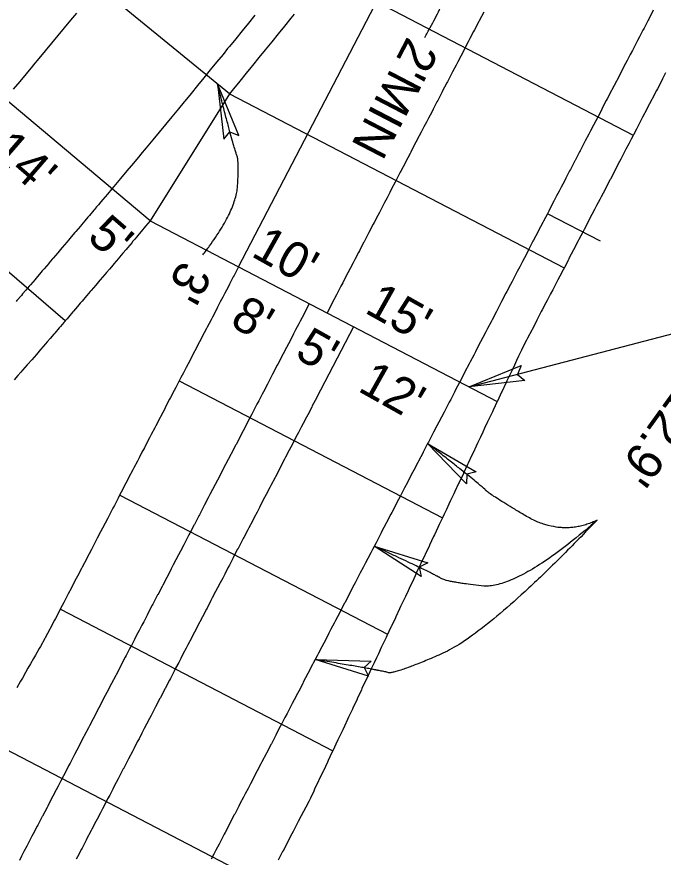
# Model space of a CAD drawing. Extents: x 2145147 to 2158018, y 137519 to 148068.
# Drawn here: x 2150427.2 to 2150492, y 143802 to 143886.4 of the extents above; entities that cross this region are included whole.
import ezdxf

# ---------------------------------------------------------------- set-up
doc = ezdxf.new("R2010")
doc.units = 0
for name, color, linetype in [('PR_Align_Ramp_B', 7, 'Continuous'), ('PR_Align_Service_C_Leader', 7, 'Continuous'), ('PR_Arrows', 7, 'Continuous'), ('PR_Dimensions', 7, 'Continuous'), ('PR_Joint_Contraction', 7, 'Continuous'), ('PR_Joint_Isolation', 7, 'Continuous'), ('PR_Joint_Long', 7, 'Continuous'), ('PR_Road_Concrete', 7, 'Continuous')]:
    doc.layers.add(name, color=color, linetype=linetype)

msp = doc.modelspace()

# ---------------------------------------------------------------- linework, layer by layer
at = {"layer": 'PR_Align_Ramp_B'}
msp.add_lwpolyline([(2150485.753, 143863.83), (2150480.431, 143866.6)], dxfattribs=at)
at = {"layer": 'PR_Align_Service_C_Leader'}
msp.add_lwpolyline([(2150472.601, 143849.219), (2150503.406, 143857.277), (2150523.033, 143884.125)], dxfattribs=at)
at = {"layer": 'PR_Arrows'}
msp.add_lwpolyline([(2150472.601, 143849.219), (2150477.794, 143851.352), (2150477.425, 143850.481), (2150478.173, 143849.866)], close=True, dxfattribs=at)
at = {"layer": 'PR_Dimensions'}
for points in [[(2150447.344, 143879.636), (2150447.998, 143874.06), (2150448.58, 143874.805), (2150449.48, 143874.449)], [(2150468.428, 143843.537), (2150473.278, 143840.709), (2150472.362, 143840.473), (2150472.328, 143839.505)], [(2150463.068, 143833.24), (2150468.431, 143831.579), (2150467.592, 143831.143), (2150467.778, 143830.193)], [(2150457.151, 143821.87), (2150462.762, 143821.705), (2150462.071, 143821.06), (2150462.504, 143820.194)]]:
    msp.add_lwpolyline(points, close=True, dxfattribs=at)
for points in [[(2150468.143, 143884.29), (2150470.819, 143888.915), (2150471.175, 143894.152), (2150470.668, 143895.218), (2150468.976, 143901.836)], [(2150445.878, 143862.457), (2150449.187, 143866.715), (2150449.543, 143871.953), (2150449.037, 143873.019), (2150447.344, 143879.636)], [(2150485.414, 143835.848), (2150481.891, 143834.132), (2150474.591, 143838.449), (2150473.817, 143839.339), (2150468.428, 143843.537)], [(2150485.414, 143835.848), (2150474.479, 143824.434), (2150464.997, 143820.349), (2150463.891, 143820.76), (2150457.151, 143821.87)], [(2150485.414, 143835.848), (2150477.393, 143828.84), (2150470.221, 143829.675), (2150469.266, 143830.367), (2150463.068, 143833.24)]]:
    msp.add_open_spline(points, degree=2, dxfattribs=at)
at = {"layer": 'PR_Joint_Contraction'}
for p, q in [((2150448.565, 143878.639), (2150428.687, 143894.877)), ((2150458.166, 143890.552), (2150489.043, 143874.482)), ((2150448.565, 143878.639), (2150482.117, 143861.177)), ((2150432.093, 143855.849), (2150411.095, 143873.864)), ((2150443.512, 143849.816), (2150469.909, 143836.078)), ((2150437.557, 143838.373), (2150464.411, 143824.397)), ((2150431.602, 143826.93), (2150458.913, 143812.716)), ((2150424.26, 143813.841), (2150452.174, 143799.313))]:
    msp.add_line(p, q, dxfattribs=at)
at = {"layer": 'PR_Joint_Isolation'}
msp.add_line((2150440.597, 143865.876), (2150419.424, 143883.685), dxfattribs=at)
msp.add_lwpolyline([(2150449.468, 143861.259), (2150475.406, 143847.76)], dxfattribs=at)
at = {"layer": 'PR_Joint_Long'}
msp.add_line((2150449.468, 143861.259), (2150470.243, 143901.177), dxfattribs=at)
for points in [[(2150491.049, 143887.003), (2150490.588, 143886.116), (2150490.53, 143886.004), (2150490.126, 143885.228), (2150490.005, 143884.996), (2150489.664, 143884.341), (2150489.481, 143883.988), (2150489.203, 143883.454), (2150488.956, 143882.98), (2150488.741, 143882.567), (2150488.431, 143881.972), (2150488.279, 143881.68), (2150487.907, 143880.964), (2150487.818, 143880.793), (2150487.382, 143879.956), (2150487.356, 143879.906), (2150486.894, 143879.019), (2150486.857, 143878.948), (2150486.433, 143878.132), (2150486.333, 143877.94), (2150485.971, 143877.245), (2150485.808, 143876.932), (2150485.509, 143876.358), (2150485.284, 143875.924), (2150485.048, 143875.471), (2150484.759, 143874.916), (2150484.586, 143874.584), (2150484.234, 143873.908), (2150484.124, 143873.697), (2150483.71, 143872.9), (2150483.663, 143872.81), (2150483.201, 143871.923), (2150483.185, 143871.892), (2150482.739, 143871.036), (2150482.66, 143870.884), (2150482.278, 143870.149), (2150482.136, 143869.876), (2150481.816, 143869.262), (2150481.611, 143868.868), (2150481.354, 143868.375), (2150481.087, 143867.86), (2150480.893, 143867.487), (2150480.562, 143866.852), (2150480.431, 143866.6), (2150480.037, 143865.844), (2150479.969, 143865.713), (2150479.513, 143864.836), (2150479.508, 143864.826), (2150479.046, 143863.939), (2150478.988, 143863.828), (2150478.584, 143863.052), (2150478.463, 143862.82), (2150478.123, 143862.165), (2150477.939, 143861.812), (2150477.661, 143861.278), (2150477.414, 143860.804), (2150477.199, 143860.391), (2150476.89, 143859.796), (2150476.738, 143859.504), (2150476.365, 143858.788), (2150476.276, 143858.617), (2150475.84, 143857.78), (2150475.814, 143857.73), (2150475.353, 143856.843), (2150475.316, 143856.772), (2150474.891, 143855.956), (2150474.791, 143855.764), (2150474.429, 143855.069), (2150474.266, 143854.756), (2150473.968, 143854.182), (2150473.742, 143853.748), (2150473.506, 143853.295), (2150473.217, 143852.74), (2150473.044, 143852.408), (2150472.693, 143851.732), (2150472.583, 143851.521), (2150472.168, 143850.724), (2150472.121, 143850.633), (2150471.659, 143849.746), (2150471.644, 143849.717), (2150471.643, 143849.716), (2150471.198, 143848.859), (2150471.119, 143848.708), (2150470.736, 143847.972), (2150470.594, 143847.7), (2150470.274, 143847.085), (2150470.069, 143846.692), (2150469.813, 143846.198), (2150469.545, 143845.684), (2150469.351, 143845.311), (2150469.02, 143844.676), (2150468.889, 143844.424), (2150468.496, 143843.668), (2150468.428, 143843.537), (2150467.971, 143842.66), (2150467.966, 143842.65), (2150467.504, 143841.763), (2150467.446, 143841.652), (2150467.043, 143840.876), (2150466.922, 143840.644), (2150466.581, 143839.989), (2150466.397, 143839.636), (2150466.119, 143839.102), (2150465.872, 143838.628), (2150465.658, 143838.215), (2150465.348, 143837.62), (2150465.196, 143837.328), (2150464.823, 143836.612), (2150464.734, 143836.441), (2150464.299, 143835.604), (2150464.273, 143835.554), (2150463.811, 143834.667), (2150463.774, 143834.596), (2150463.349, 143833.779), (2150463.249, 143833.588), (2150462.887, 143832.892), (2150462.725, 143832.58), (2150462.426, 143832.005), (2150462.2, 143831.572), (2150461.964, 143831.118), (2150461.675, 143830.564), (2150461.502, 143830.231), (2150461.151, 143829.556), (2150461.041, 143829.344), (2150460.626, 143828.547), (2150460.579, 143828.457), (2150460.117, 143827.57), (2150460.102, 143827.539), (2150459.656, 143826.683), (2150459.577, 143826.531), (2150459.194, 143825.796), (2150459.052, 143825.523), (2150458.732, 143824.909), (2150458.528, 143824.515), (2150458.271, 143824.022), (2150458.003, 143823.507), (2150457.809, 143823.135), (2150457.478, 143822.499), (2150457.347, 143822.248), (2150456.954, 143821.491), (2150456.886, 143821.361), (2150456.429, 143820.483), (2150456.424, 143820.474), (2150455.962, 143819.587), (2150455.905, 143819.475), (2150455.501, 143818.7), (2150455.38, 143818.467), (2150455.039, 143817.813), (2150454.855, 143817.459), (2150454.577, 143816.926), (2150454.331, 143816.451), (2150454.116, 143816.038), (2150453.806, 143815.443), (2150453.654, 143815.151), (2150453.281, 143814.435), (2150453.192, 143814.264), (2150452.757, 143813.427), (2150452.731, 143813.377), (2150452.269, 143812.49), (2150452.232, 143812.419), (2150451.807, 143811.603), (2150451.708, 143811.411), (2150451.346, 143810.716), (2150451.183, 143810.403), (2150450.884, 143809.829), (2150450.658, 143809.395), (2150450.422, 143808.942), (2150450.134, 143808.387), (2150449.961, 143808.055), (2150449.609, 143807.379), (2150449.499, 143807.168), (2150449.084, 143806.371), (2150449.037, 143806.281), (2150448.576, 143805.394), (2150448.56, 143805.363), (2150448.114, 143804.507), (2150448.035, 143804.355), (2150447.652, 143803.62), (2150447.511, 143803.347), (2150447.191, 143802.733), (2150446.986, 143802.339), (2150446.729, 143801.846)], [(2150433.215, 143886.728), (2150432.624, 143886.01), (2150431.989, 143885.24), (2150431.353, 143884.47), (2150430.717, 143883.7), (2150430.08, 143882.932), (2150429.443, 143882.163), (2150428.887, 143881.495), (2150428.805, 143881.396), (2150428.166, 143880.629), (2150427.526, 143879.862), (2150426.886, 143879.096)], [(2150451.09, 143886.513), (2150450.456, 143885.727), (2150449.821, 143884.941), (2150449.185, 143884.155), (2150448.55, 143883.372), (2150448.377, 143883.16), (2150447.911, 143882.586), (2150447.273, 143881.802), (2150446.635, 143881.019), (2150445.996, 143880.237), (2150445.356, 143879.454), (2150444.715, 143878.673), (2150444.076, 143877.894), (2150444.029, 143877.837), (2150443.432, 143877.111), (2150442.79, 143876.332), (2150442.146, 143875.552), (2150441.502, 143874.774), (2150440.858, 143873.996), (2150440.213, 143873.218), (2150439.652, 143872.543), (2150439.565, 143872.439), (2150438.92, 143871.665), (2150438.272, 143870.889), (2150437.624, 143870.113), (2150436.977, 143869.34), (2150436.768, 143869.091), (2150436.765, 143869.087), (2150436.327, 143868.566), (2150436.315, 143868.551), (2150435.866, 143868.016), (2150435.676, 143867.791), (2150435.414, 143867.48), (2150435.239, 143867.271), (2150435.026, 143867.018), (2150434.962, 143866.942), (2150434.512, 143866.409), (2150434.374, 143866.245), (2150434.06, 143865.873), (2150433.723, 143865.474), (2150433.607, 143865.337), (2150433.156, 143864.804), (2150433.069, 143864.701), (2150432.702, 143864.269), (2150432.416, 143863.932), (2150432.248, 143863.734), (2150431.797, 143863.202), (2150431.761, 143863.16), (2150431.342, 143862.668), (2150431.107, 143862.391), (2150430.888, 143862.134), (2150430.796, 143862.027), (2150430.452, 143861.623), (2150430.432, 143861.599), (2150429.979, 143861.069), (2150429.795, 143860.854), (2150429.523, 143860.535), (2150429.14, 143860.087), (2150429.067, 143860.002), (2150428.613, 143859.472), (2150428.481, 143859.318), (2150428.156, 143858.939), (2150427.824, 143858.552), (2150427.699, 143858.407), (2150427.244, 143857.878), (2150427.164, 143857.785)], [(2150455.035, 143886.632), (2150454.696, 143886.209), (2150454.061, 143885.42), (2150453.426, 143884.631), (2150452.79, 143883.842), (2150452.153, 143883.054), (2150451.516, 143882.267), (2150450.878, 143881.48), (2150450.707, 143881.27), (2150450.239, 143880.693), (2150449.599, 143879.908), (2150448.959, 143879.122), (2150448.565, 143878.639), (2150440.597, 143865.876)], [(2150474.05, 143886.831), (2150473.589, 143885.944), (2150473.552, 143885.873), (2150473.127, 143885.057), (2150473.027, 143884.865), (2150472.665, 143884.17), (2150472.502, 143883.857), (2150472.204, 143883.283), (2150471.978, 143882.849), (2150471.742, 143882.396), (2150471.453, 143881.841), (2150471.28, 143881.509), (2150470.928, 143880.833), (2150470.819, 143880.622), (2150470.404, 143879.825), (2150470.357, 143879.735), (2150469.895, 143878.848), (2150469.879, 143878.817), (2150469.434, 143877.961), (2150469.355, 143877.809), (2150468.972, 143877.074), (2150468.83, 143876.801), (2150468.51, 143876.187), (2150468.305, 143875.793), (2150468.049, 143875.3), (2150467.781, 143874.785), (2150467.587, 143874.413), (2150467.256, 143873.777), (2150467.125, 143873.525), (2150466.731, 143872.769), (2150466.663, 143872.638), (2150466.207, 143871.761), (2150466.202, 143871.751), (2150465.74, 143870.864), (2150465.682, 143870.753), (2150465.278, 143869.977), (2150465.158, 143869.745), (2150464.817, 143869.09), (2150464.633, 143868.737), (2150464.355, 143868.203), (2150464.108, 143867.729), (2150463.893, 143867.316), (2150463.584, 143866.721), (2150463.432, 143866.429), (2150463.059, 143865.713), (2150462.97, 143865.542), (2150462.534, 143864.705), (2150462.508, 143864.655), (2150462.047, 143863.768), (2150462.01, 143863.697), (2150461.585, 143862.881), (2150461.485, 143862.689), (2150461.123, 143861.994), (2150460.961, 143861.681), (2150460.662, 143861.107), (2150460.436, 143860.673), (2150460.2, 143860.22), (2150459.911, 143859.665), (2150459.738, 143859.333), (2150459.387, 143858.657), (2150459.277, 143858.446), (2150458.862, 143857.649), (2150458.815, 143857.559), (2150458.338, 143856.643)], [(2150456.564, 143857.566), (2150456.118, 143856.708), (2150456.04, 143856.558), (2150455.656, 143855.821), (2150455.514, 143855.549), (2150455.193, 143854.932), (2150454.989, 143854.539), (2150454.733, 143854.047), (2150454.465, 143853.533), (2150454.271, 143853.16), (2150453.94, 143852.524), (2150453.415, 143851.515), (2150453.348, 143851.385), (2150452.884, 143850.494), (2150452.879, 143850.484), (2150452.425, 143849.613), (2150452.366, 143849.501), (2150451.963, 143848.724), (2150451.842, 143848.493), (2150451.501, 143847.838), (2150451.317, 143847.485), (2150451.038, 143846.949), (2150450.792, 143846.475), (2150450.578, 143846.064), (2150450.268, 143845.469), (2150450.116, 143845.177), (2150449.743, 143844.461), (2150449.654, 143844.289), (2150449.218, 143843.452), (2150449.193, 143843.402), (2150448.731, 143842.516), (2150448.694, 143842.445), (2150448.168, 143841.435), (2150447.808, 143840.74), (2150447.645, 143840.429), (2150447.346, 143839.854), (2150447.12, 143839.421), (2150446.595, 143838.411), (2150446.423, 143838.079), (2150446.071, 143837.404), (2150445.961, 143837.192), (2150445.545, 143836.394), (2150445.497, 143836.302), (2150445.042, 143835.427), (2150445.027, 143835.397), (2150444.577, 143834.533), (2150444.498, 143834.382), (2150444.114, 143833.644), (2150443.971, 143833.37), (2150443.653, 143832.757), (2150443.448, 143832.364), (2150443.191, 143831.871), (2150442.923, 143831.356), (2150442.729, 143830.983), (2150442.399, 143830.347), (2150442.268, 143830.097), (2150441.875, 143829.341), (2150441.807, 143829.211), (2150441.361, 143828.356), (2150441.356, 143828.346), (2150440.882, 143827.433), (2150440.824, 143827.322), (2150440.421, 143826.548), (2150440.3, 143826.315), (2150439.958, 143825.66), (2150439.775, 143825.306), (2150439.498, 143824.775), (2150439.251, 143824.299), (2150439.036, 143823.887), (2150438.726, 143823.292), (2150438.574, 143822.999), (2150438.202, 143822.283), (2150438.113, 143822.113), (2150437.677, 143821.275), (2150437.651, 143821.225), (2150437.189, 143820.339), (2150437.152, 143820.267), (2150436.728, 143819.451), (2150436.266, 143818.565), (2150436.103, 143818.252), (2150435.803, 143817.676), (2150435.578, 143817.242), (2150435.343, 143816.791), (2150435.054, 143816.236), (2150434.881, 143815.904), (2150434.529, 143815.228), (2150434.419, 143815.016), (2150434.005, 143814.22), (2150433.959, 143814.131), (2150433.494, 143813.24), (2150433.479, 143813.209), (2150433.034, 143812.355), (2150432.573, 143811.468), (2150432.431, 143811.196), (2150432.111, 143810.582), (2150431.906, 143810.188), (2150431.648, 143809.694), (2150431.382, 143809.179), (2150431.188, 143808.808), (2150430.857, 143808.172), (2150430.726, 143807.921), (2150430.333, 143807.165), (2150430.264, 143807.034), (2150429.8, 143806.14), (2150429.796, 143806.131), (2150429.342, 143805.26), (2150429.284, 143805.149), (2150428.879, 143804.372), (2150428.758, 143804.139), (2150428.418, 143803.484), (2150428.234, 143803.132), (2150427.956, 143802.598), (2150427.709, 143802.124), (2150427.494, 143801.71)], [(2150461.003, 143855.256), (2150457.283, 143848.117), (2150457.278, 143848.106), (2150456.865, 143847.314), (2150456.804, 143847.196), (2150456.399, 143846.416), (2150456.281, 143846.19), (2150455.939, 143845.534), (2150455.755, 143845.18), (2150455.477, 143844.646), (2150455.224, 143844.162), (2150455.01, 143843.748), (2150454.705, 143843.163), (2150454.553, 143842.871), (2150454.18, 143842.155), (2150454.088, 143841.978), (2150453.652, 143841.14), (2150453.629, 143841.094), (2150453.169, 143840.212), (2150453.131, 143840.138), (2150452.711, 143839.331), (2150452.611, 143839.14), (2150452.239, 143838.426), (2150452.077, 143838.114), (2150451.784, 143837.55), (2150451.558, 143837.116), (2150451.321, 143836.661), (2150451.031, 143836.106), (2150450.855, 143835.766), (2150450.502, 143835.088), (2150450.394, 143834.879), (2150449.986, 143834.096), (2150449.94, 143834.007), (2150449.393, 143832.957), (2150449.378, 143832.926), (2150449.012, 143832.223), (2150448.933, 143832.071), (2150448.551, 143831.338), (2150448.409, 143831.065), (2150448.084, 143830.441), (2150447.88, 143830.048), (2150447.629, 143829.566), (2150447.361, 143829.052), (2150447.167, 143828.68), (2150446.837, 143828.046), (2150446.703, 143827.789), (2150446.313, 143827.037), (2150446.248, 143826.913), (2150445.86, 143826.169), (2150445.856, 143826.161), (2150445.293, 143825.081), (2150445.237, 143824.971), (2150444.856, 143824.239), (2150444.735, 143824.007), (2150444.395, 143823.355), (2150444.212, 143823.001), (2150443.93, 143822.461), (2150443.682, 143821.981), (2150443.473, 143821.581), (2150443.163, 143820.986), (2150443.011, 143820.694), (2150442.638, 143819.978), (2150442.546, 143819.801), (2150442.11, 143818.963), (2150442.087, 143818.917), (2150441.627, 143818.035), (2150441.59, 143817.964), (2150441.153, 143817.125), (2150441.054, 143816.933), (2150440.703, 143816.26), (2150440.541, 143815.947), (2150440.241, 143815.373), (2150440.016, 143814.939), (2150439.776, 143814.478), (2150439.488, 143813.924), (2150439.319, 143813.599), (2150438.967, 143812.924), (2150438.857, 143812.713), (2150438.444, 143811.92), (2150438.395, 143811.826), (2150437.921, 143810.913), (2150437.908, 143810.888), (2150437.47, 143810.047), (2150437.391, 143809.895), (2150437.001, 143809.147), (2150436.86, 143808.874), (2150436.548, 143808.276), (2150436.343, 143807.882), (2150436.087, 143807.39), (2150435.819, 143806.876), (2150435.622, 143806.497), (2150435.293, 143805.863), (2150435.165, 143805.619), (2150434.765, 143804.85), (2150434.698, 143804.721), (2150434.199, 143803.764), (2150434.191, 143803.748), (2150433.78, 143802.956), (2150433.724, 143802.849), (2150433.318, 143802.069), (2150433.197, 143801.837)]]:
    msp.add_lwpolyline(points, dxfattribs=at)
at = {"layer": 'PR_Road_Concrete'}
msp.add_line((2150440.597, 143865.876), (2150449.468, 143861.259), dxfattribs=at)
for points in [[(2150492.289, 143880.721), (2150491.979, 143880.126), (2150491.828, 143879.834), (2150491.455, 143879.118), (2150491.366, 143878.947), (2150490.93, 143878.11), (2150490.904, 143878.06), (2150490.443, 143877.172), (2150490.406, 143877.101), (2150489.981, 143876.285), (2150489.881, 143876.093), (2150489.519, 143875.398), (2150489.356, 143875.085), (2150489.058, 143874.511), (2150488.832, 143874.077), (2150488.596, 143873.624), (2150488.307, 143873.069), (2150488.134, 143872.737), (2150487.782, 143872.061), (2150487.673, 143871.85), (2150487.258, 143871.053), (2150487.211, 143870.963), (2150486.749, 143870.076), (2150486.733, 143870.045), (2150486.287, 143869.189), (2150486.209, 143869.037), (2150485.826, 143868.302), (2150485.684, 143868.029), (2150485.364, 143867.415), (2150485.159, 143867.021), (2150484.902, 143866.528), (2150484.635, 143866.013), (2150484.441, 143865.641), (2150484.11, 143865.005), (2150483.979, 143864.754), (2150483.585, 143863.997), (2150483.517, 143863.867), (2150483.061, 143862.989), (2150483.056, 143862.98), (2150482.594, 143862.093), (2150482.536, 143861.981), (2150482.132, 143861.206), (2150482.012, 143860.973), (2150481.671, 143860.318), (2150481.487, 143859.965), (2150481.209, 143859.431), (2150480.962, 143858.957), (2150480.747, 143858.544), (2150480.438, 143857.949), (2150480.286, 143857.657), (2150479.913, 143856.941), (2150479.824, 143856.77), (2150479.388, 143855.933), (2150479.362, 143855.883), (2150478.901, 143854.996), (2150478.864, 143854.925), (2150478.439, 143854.109), (2150478.339, 143853.917), (2150477.977, 143853.222), (2150477.827, 143852.903), (2150477.551, 143852.317), (2150477.343, 143851.874), (2150477.125, 143851.411), (2150476.859, 143850.845), (2150476.699, 143850.505), (2150476.374, 143849.816), (2150476.273, 143849.6), (2150475.89, 143848.787), (2150475.847, 143848.694), (2150475.42, 143847.789), (2150475.406, 143847.759), (2150475.406, 143847.758), (2150474.994, 143846.883), (2150474.921, 143846.729), (2150474.568, 143845.978), (2150474.437, 143845.7), (2150474.142, 143845.072), (2150473.953, 143844.671), (2150473.716, 143844.167), (2150473.468, 143843.642), (2150473.289, 143843.261), (2150472.984, 143842.613), (2150472.863, 143842.356), (2150472.5, 143841.584), (2150472.437, 143841.45), (2150472.015, 143840.555), (2150472.011, 143840.545), (2150471.585, 143839.639), (2150471.531, 143839.526), (2150471.158, 143838.734), (2150471.047, 143838.497), (2150470.732, 143837.828), (2150470.563, 143837.468), (2150470.306, 143836.923), (2150470.078, 143836.439), (2150469.88, 143836.017), (2150469.594, 143835.41), (2150469.454, 143835.112), (2150469.11, 143834.381), (2150469.028, 143834.206), (2150468.625, 143833.352), (2150468.601, 143833.301), (2150468.175, 143832.395), (2150468.141, 143832.323), (2150467.749, 143831.49), (2150467.657, 143831.294), (2150467.323, 143830.584), (2150467.172, 143830.265), (2150466.897, 143829.679), (2150466.688, 143829.236), (2150466.47, 143828.773), (2150466.204, 143828.207), (2150466.044, 143827.868), (2150465.72, 143827.178), (2150465.618, 143826.962), (2150465.235, 143826.149), (2150465.192, 143826.056), (2150464.766, 143825.151), (2150464.751, 143825.12), (2150464.339, 143824.245), (2150464.267, 143824.091), (2150463.913, 143823.34), (2150463.782, 143823.062), (2150463.487, 143822.434), (2150463.298, 143822.033), (2150463.061, 143821.529), (2150462.814, 143821.004), (2150462.635, 143820.623), (2150462.329, 143819.975), (2150462.209, 143819.718), (2150461.845, 143818.946), (2150461.782, 143818.812), (2150461.361, 143817.917), (2150461.356, 143817.907), (2150460.93, 143817.001), (2150460.876, 143816.888), (2150460.504, 143816.096), (2150460.392, 143815.859), (2150460.078, 143815.19), (2150459.908, 143814.83), (2150459.651, 143814.285), (2150459.424, 143813.801), (2150459.225, 143813.379), (2150458.939, 143812.772), (2150458.799, 143812.474), (2150458.455, 143811.743), (2150458.373, 143811.568), (2150457.971, 143810.714), (2150457.947, 143810.663), (2150457.52, 143809.757), (2150457.486, 143809.685), (2150457.094, 143808.852), (2150457.002, 143808.656), (2150456.668, 143807.946), (2150456.505, 143807.633), (2150456.206, 143807.059), (2150455.981, 143806.625), (2150455.745, 143806.172), (2150455.456, 143805.617), (2150455.283, 143805.285), (2150454.931, 143804.609), (2150454.821, 143804.398), (2150454.407, 143803.601), (2150454.36, 143803.511), (2150453.898, 143802.624), (2150453.882, 143802.593), (2150453.436, 143801.737)], [(2150440.597, 143865.876), (2150440.156, 143865.35), (2150440.145, 143865.337), (2150439.693, 143864.798), (2150439.503, 143864.573), (2150439.24, 143864.26), (2150439.064, 143864.051), (2150438.849, 143863.796), (2150438.787, 143863.722), (2150438.333, 143863.184), (2150438.195, 143863.02), (2150437.879, 143862.646), (2150437.54, 143862.245), (2150437.425, 143862.109), (2150436.971, 143861.572), (2150436.885, 143861.47), (2150436.516, 143861.035), (2150436.228, 143860.696), (2150436.061, 143860.499), (2150435.605, 143859.963), (2150435.572, 143859.923), (2150435.15, 143859.427), (2150434.914, 143859.15), (2150434.693, 143858.891), (2150434.603, 143858.784), (2150434.256, 143858.377), (2150434.237, 143858.356), (2150433.78, 143857.82), (2150433.597, 143857.606), (2150433.323, 143857.286), (2150432.937, 143856.834), (2150432.866, 143856.751), (2150432.408, 143856.217), (2150432.277, 143856.064), (2150431.95, 143855.683), (2150431.616, 143855.294), (2150431.492, 143855.149), (2150431.033, 143854.616), (2150430.954, 143854.524), (2150430.574, 143854.082), (2150430.292, 143853.755), (2150430.115, 143853.55), (2150430.11, 143853.544), (2150429.655, 143853.017), (2150429.629, 143852.987), (2150429.195, 143852.485), (2150428.965, 143852.219), (2150428.735, 143851.953), (2150428.301, 143851.452), (2150428.274, 143851.421), (2150427.813, 143850.889), (2150427.636, 143850.685), (2150427.352, 143850.358), (2150426.97, 143849.919)], [(2150449.468, 143861.259), (2150449.021, 143860.401), (2150448.942, 143860.25), (2150448.56, 143859.514), (2150448.418, 143859.241), (2150448.098, 143858.627), (2150447.893, 143858.233), (2150447.636, 143857.74), (2150447.368, 143857.225), (2150447.175, 143856.853), (2150446.844, 143856.217), (2150446.713, 143855.966), (2150446.319, 143855.209), (2150446.251, 143855.079), (2150445.795, 143854.201), (2150445.79, 143854.192), (2150445.328, 143853.305), (2150445.27, 143853.193), (2150444.866, 143852.418), (2150444.745, 143852.185), (2150444.405, 143851.531), (2150444.221, 143851.177), (2150443.943, 143850.644), (2150443.696, 143850.169), (2150443.481, 143849.756), (2150443.171, 143849.161), (2150443.02, 143848.869), (2150442.647, 143848.153), (2150442.558, 143847.982), (2150442.122, 143847.145), (2150442.096, 143847.095), (2150441.635, 143846.208), (2150441.598, 143846.137), (2150441.173, 143845.321), (2150441.073, 143845.129), (2150440.711, 143844.434), (2150440.548, 143844.121), (2150440.25, 143843.547), (2150440.024, 143843.113), (2150439.788, 143842.66), (2150439.499, 143842.105), (2150439.326, 143841.773), (2150438.974, 143841.097), (2150438.865, 143840.886), (2150438.45, 143840.089), (2150438.403, 143839.999), (2150437.941, 143839.112), (2150437.925, 143839.081), (2150437.48, 143838.225), (2150437.401, 143838.073), (2150437.018, 143837.338), (2150436.876, 143837.065), (2150436.556, 143836.451), (2150436.351, 143836.057), (2150436.094, 143835.564), (2150435.827, 143835.049), (2150435.633, 143834.677), (2150435.302, 143834.041), (2150435.171, 143833.79), (2150434.777, 143833.033), (2150434.709, 143832.903), (2150434.253, 143832.025), (2150434.248, 143832.015), (2150433.786, 143831.128), (2150433.728, 143831.017), (2150433.324, 143830.241), (2150433.204, 143830.009), (2150432.863, 143829.354), (2150432.679, 143829.001), (2150432.401, 143828.467), (2150432.154, 143827.993), (2150431.939, 143827.58), (2150431.63, 143826.985), (2150431.478, 143826.693), (2150431.105, 143825.977), (2150431.016, 143825.806), (2150430.58, 143824.969), (2150430.554, 143824.919), (2150430.093, 143824.032), (2150430.053, 143823.962), (2150429.596, 143823.163), (2150429.488, 143822.975), (2150429.098, 143822.295), (2150428.923, 143821.988), (2150428.601, 143821.426), (2150428.358, 143821.001), (2150428.104, 143820.558), (2150427.793, 143820.014), (2150427.607, 143819.689), (2150427.228, 143819.027)]]:
    msp.add_lwpolyline(points, dxfattribs=at)

# ---------------------------------------------------------------- texts
at = {"layer": 'PR_Dimensions'}
for s, rotation, p in [("2'MIN", 242.53748, (2150466.43, 143884.478)), ("14'", 319.1685, (2150424.463, 143872.551)), ("5'", 319.1685, (2150434.163, 143864.062)), ("10'", 330.70293, (2150450.614, 143862.396)), ("3'", 242.53748, (2150443.706, 143862.058)), ("15'", 330.70293, (2150461.991, 143856.732)), ("8'", 330.70293, (2150448.476, 143855.433)), ("5'", 330.70293, (2150454.979, 143852.23)), ("12'", 330.70293, (2150461.314, 143848.866)), ("12.9'", 234.2994, (2150493.37, 143849.318))]:
    msp.add_text(s, height=3.6, rotation=rotation, dxfattribs=at).set_placement(p)

doc.saveas('drawing.dxf')
